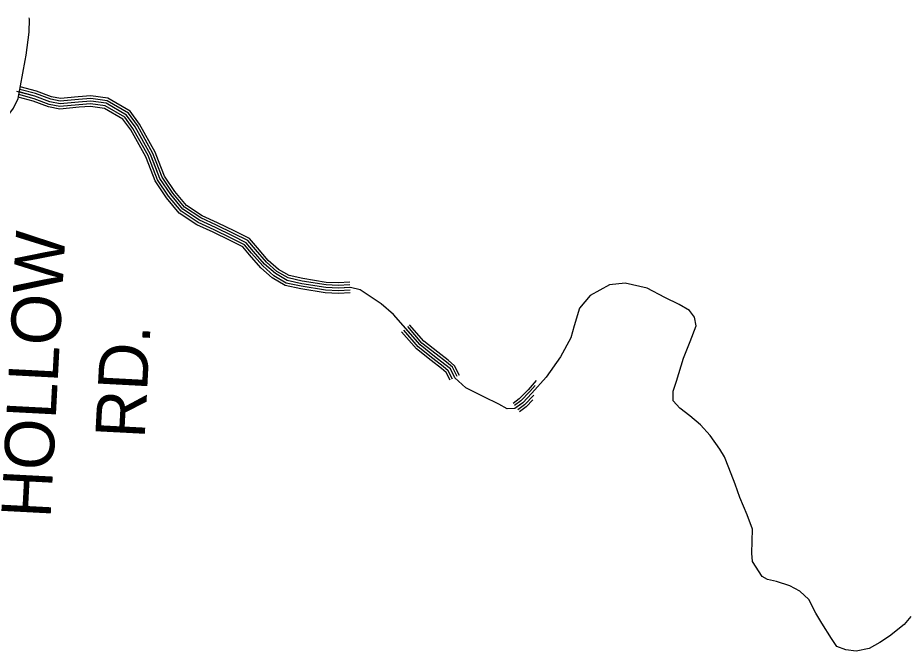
# Model space of a CAD drawing. Extents: x 1551132 to 1791609, y 378168 to 563823.
# Drawn here: x 1683490 to 1690138, y 392618 to 397359 of the extents above; entities that cross this region are included whole.
import ezdxf

# ---------------------------------------------------------------- set-up
doc = ezdxf.new("R2010")
doc.units = 0
for name, color, linetype in [('DESIGN - ROW - Right-of-Way and Easement Labels', 7, 'Continuous'), ('SURVEY - DRAINAGE - Natural Features', 7, 'Continuous'), ('SURVEY - PROPERTY - Owners', 7, 'Continuous')]:
    doc.layers.add(name, color=color, linetype=linetype)

msp = doc.modelspace()

# ---------------------------------------------------------------- linework, layer by layer
at = {"layer": 'SURVEY - DRAINAGE - Natural Features'}
for points in [[(1688443.044, 394437.967), (1688393.886, 394492.794), (1688393.078, 394564.837), (1688420.336, 394638.414), (1688471.268, 394811.627), (1688521.4, 394936.847), (1688565.374, 395052.159), (1688554.45, 395118.36), (1688515.242, 395169.028), (1688437.886, 395214.313), (1688330.605, 395266.097), (1688199.566, 395334.283), (1688035.995, 395372.992), (1687917.64, 395360.933), (1687774.101, 395279.273), (1687694.461, 395186.553), (1687654.204, 395053.175), (1687628.688, 394963.564), (1687552.223, 394820.777), (1687443.559, 394668.515), (1687337.428, 394548.228), (1687268.163, 394477.343), (1687209.372, 394434.3), (1687151.282, 394433.25), (1687089.75, 394466.276), (1686978.528, 394522.127), (1686843.448, 394588.379), (1686760.591, 394663.772), (1686727.65, 394730.333), (1686686.168, 394765.033), (1686609.053, 394824.318), (1686500.331, 394910.137), (1686301.869, 395139.485), (1686209.071, 395219.045), (1686052.567, 395321.656), (1685980.785, 395340.848), (1685888.595, 395336.365), (1685794.531, 395339.915), (1685614.777, 395368.891), (1685505.029, 395392.708), (1685417.765, 395444.159), (1685336.842, 395515.519), (1685254.31, 395610.913), (1685199.32, 395675.84), (1685096.039, 395727.558), (1684968.9, 395789.676), (1684849.637, 395843.653), (1684724.84, 395925.738), (1684634.533, 396035.266), (1684552.435, 396156.661), (1684483.312, 396335.857), (1684368.573, 396541.821), (1684303.966, 396630.915), (1684151.228, 396719.459), (1684035.348, 396735.376), (1683945.116, 396728.859), (1683806.711, 396715.134), (1683730.863, 396730.392), (1683617.407, 396772.277), (1683483.836, 396808.486)], [(1684506.945, 396274.589), (1684483.312, 396335.857), (1684368.573, 396541.821), (1684303.966, 396630.915), (1684151.228, 396719.459), (1684035.348, 396735.376), (1683945.116, 396728.859), (1683806.711, 396715.134), (1683730.863, 396730.392), (1683617.407, 396772.277), (1683500.694, 396803.919)], [(1684525.603, 396281.789), (1684501.47, 396344.366), (1684385.464, 396552.596), (1684317.666, 396646.09), (1684157.853, 396738.734), (1684035.998, 396755.476), (1683943.408, 396748.784), (1683807.72, 396735.334), (1683736.33, 396749.693), (1683623.499, 396791.344), (1683504.502, 396823.603)], [(1684543.327, 396288.623), (1684518.711, 396352.449), (1684401.514, 396562.838), (1684330.682, 396660.507), (1684164.145, 396757.051), (1684036.606, 396774.569), (1683941.783, 396767.718), (1683808.678, 396754.518), (1683741.53, 396768.027), (1683629.282, 396809.469), (1683507.552, 396842.462)], [(1684469.629, 396260.188), (1684447.005, 396318.84), (1684334.791, 396520.27), (1684276.567, 396600.564), (1684137.979, 396680.899), (1684034.056, 396695.175), (1683948.533, 396689), (1683804.695, 396674.732), (1683719.93, 396691.791), (1683605.224, 396734.134), (1683493.444, 396764.435)], [(1684488.287, 396267.389), (1684465.154, 396327.349), (1684351.682, 396531.046), (1684290.267, 396615.739), (1684144.603, 396700.183), (1684034.698, 396715.275), (1683946.825, 396708.933), (1683805.703, 396694.933), (1683725.397, 396711.092), (1683611.316, 396753.209), (1683497.385, 396784.094)], [(1685977.277, 395300.631), (1685888.812, 395296.33), (1685790.581, 395300.03), (1685607.344, 395329.573), (1685490.255, 395354.982), (1685394.165, 395411.633), (1685308.359, 395487.302), (1685223.928, 395584.896), (1685174.087, 395643.739), (1685078.306, 395691.699), (1684951.867, 395753.475), (1684830.279, 395808.502), (1684697.815, 395895.637), (1684602.467, 396011.282), (1684516.753, 396138.019), (1684469.621, 396260.213)], [(1685976.31, 395320.606), (1685888.704, 395316.348), (1685792.556, 395319.973), (1685611.06, 395349.232), (1685497.646, 395373.841), (1685405.965, 395427.9), (1685322.6, 395501.411), (1685239.119, 395597.905), (1685186.704, 395659.79), (1685087.173, 395709.633), (1684960.384, 395771.576), (1684839.962, 395826.077), (1684711.331, 395910.688), (1684618.5, 396023.274), (1684534.594, 396147.344), (1684488.279, 396267.414)], [(1685975.335, 395340.582), (1685888.595, 395336.365), (1685794.531, 395339.915), (1685614.777, 395368.891), (1685505.029, 395392.708), (1685417.765, 395444.159), (1685336.842, 395515.519), (1685254.31, 395610.913), (1685199.32, 395675.84), (1685096.039, 395727.558), (1684968.9, 395789.676), (1684849.637, 395843.653), (1684724.84, 395925.738), (1684634.533, 396035.266), (1684552.435, 396156.661), (1684506.936, 396274.614)], [(1685974.36, 395360.557), (1685888.487, 395356.382), (1685796.506, 395359.857), (1685618.493, 395388.549), (1685512.413, 395411.575), (1685429.564, 395460.418), (1685351.083, 395529.628), (1685269.502, 395623.922), (1685211.936, 395691.891), (1685104.906, 395745.484), (1684977.417, 395807.777), (1684859.311, 395861.228), (1684738.348, 395940.789), (1684650.566, 396047.258), (1684570.277, 396165.978), (1684525.594, 396281.814)], [(1685973.443, 395379.533), (1685888.387, 395375.399), (1685798.381, 395378.799), (1685622.018, 395407.225), (1685519.429, 395429.492), (1685440.773, 395475.868), (1685364.608, 395543.028), (1685283.935, 395636.281), (1685223.919, 395707.141), (1685113.33, 395762.517), (1684985.5, 395824.969), (1684868.511, 395877.92), (1684751.189, 395955.089), (1684665.799, 396058.65), (1684587.226, 396174.836), (1684543.319, 396288.648)], [(1686795.29, 394681.581), (1686758.966, 394754.983), (1686710.576, 394795.468), (1686633.019, 394855.086), (1686527.397, 394938.455), (1686422.224, 395059.999)], [(1686724.492, 394646.539), (1686695.535, 394705.049), (1686661.135, 394733.824), (1686584.47, 394792.759), (1686472.565, 394881.095), (1686362.484, 395008.306)], [(1686742.417, 394655.406), (1686711.592, 394717.691), (1686673.652, 394749.425), (1686596.762, 394808.543), (1686486.448, 394895.612), (1686377.609, 395021.398)], [(1686760.341, 394664.281), (1686727.65, 394730.333), (1686686.168, 394765.033), (1686609.053, 394824.318), (1686500.331, 394910.137), (1686392.733, 395034.482)], [(1686778.266, 394673.156), (1686743.708, 394742.975), (1686698.684, 394780.642), (1686621.345, 394840.094), (1686514.214, 394924.663), (1686407.858, 395047.566)], [(1687369.969, 394644.056), (1687308.845, 394574.779), (1687242.522, 394506.91), (1687196.464, 394473.184)], [(1687362.619, 394607.013), (1687322.77, 394561.845), (1687255.013, 394492.502), (1687207.689, 394457.851)], [(1687357.577, 394571.062), (1687337.428, 394548.228), (1687268.163, 394477.343), (1687219.505, 394441.717)], [(1687350.894, 394533.386), (1687281.312, 394462.184), (1687231.322, 394425.583)], [(1687345.211, 394498.96), (1687294.462, 394447.017), (1687243.138, 394409.441)], [(1690173.452, 392876.927), (1690122.404, 392817.75), (1690012.798, 392729.523), (1689941.933, 392682.68), (1689861.085, 392637.995), (1689764.62, 392617.578), (1689686.672, 392626.862), (1689619.04, 392653.987), (1689579.958, 392712.656), (1689507.768, 392827.884), (1689460.944, 392902.677), (1689408.587, 393005.572), (1689341.505, 393066.698), (1689268.099, 393107.924), (1689166.484, 393139.608), (1689100.653, 393154.7), (1689058.97, 393177.393), (1688986.722, 393288.621), (1688981.739, 393350.722), (1688986.73, 393530.702), (1688948.481, 393639.371), (1688892.541, 393768.333), (1688858.159, 393868.936), (1688810.101, 393989.772), (1688779.427, 394072.299), (1688742.345, 394130.934), (1688669.93, 394232.162), (1688599.148, 394311.356), (1688518.158, 394378.707), (1688443.044, 394437.967)]]:
    msp.add_lwpolyline(points, dxfattribs=at)
at = {"layer": 'SURVEY - PROPERTY - Owners'}
msp.add_lwpolyline([(1682297.329, 395739.69), (1682451.493, 395739.965), (1682597.189, 395736.915), (1682681.587, 395754.841), (1682734.161, 395779.117), (1682764.469, 395793.109), (1682844.892, 395855.427), (1682926.948, 395911.404), (1683003.188, 395963.047), (1683051.512, 396008.456), (1683093.744, 396055.457), (1683142.135, 396146.552), (1683162.451, 396184.803), (1683274.415, 396368.566), (1683361.772, 396514.52), (1683394.079, 396583.005), (1683414.237, 396625.723), (1683458.711, 396683.699), (1683492.019, 396754.918), (1683546.109, 397038.975), (1683551.342, 397078.81), (1683574.159, 397252.406), (1683577.1, 397350.083), (1683574.667, 397359.475)], dxfattribs=at)

# ---------------------------------------------------------------- texts
at = {"layer": 'DESIGN - ROW - Right-of-Way and Easement Labels'}
for s, p in [('HOLLOW', (1683734.695, 393608.635)), ('RD.', (1684438.904, 394204.584))]:
    msp.add_text(s, height=370.0092, rotation=87.0001222, dxfattribs=at).set_placement(p)

doc.saveas('drawing.dxf')
